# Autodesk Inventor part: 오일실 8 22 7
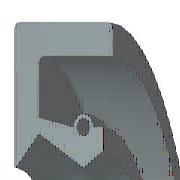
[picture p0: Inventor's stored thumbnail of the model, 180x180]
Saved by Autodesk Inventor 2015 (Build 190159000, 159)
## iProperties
IsCustomPart: 1
Created: 2012-02
Part Number: 오일실 8 22 7
Material: 고무
Description: 오일-실
Document SubType Name: Modeling
Standard: KS B 2804
Designer: mduedu
Standards Organization: KS
Language: ko-KR
Size Designation: D - 8 22 7
Categories: <MemberInstance><Categories><Category DisplayName="샤프트 부품" InternalName="7f7aeb1f-a693-4053-b835-cee3144e0d98" Mnemonic="SHFT"><Category DisplayName="실링" Intern
Density: 0.93 g/cm^3
Appearance: 고무 - 검은색 - 버전 1.1
Mass: 1.28441 g
Surface Area: 18.2787 cm^2
Volume: 1.38108 cm^3
Author: mduedu
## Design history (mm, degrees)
revolve "본체" stored, may be unused: angle "d17" = 90 deg
revolve "스프링1" stored, may be unused: angle "d18" = 90 deg
body "Solid1"
sketch "스케치1"
  geometry: L1 (0, 11)-(7, 11); L2 (7, 9.25)-(1.75, 9.25); L3 (1.75, 5.75)-(4.9, 4); L4 (4.9, 4)-(0, 4); L5 (0, 0)-(9.586, 0) reference; L6 (4.9, 4)-(6.3, 4.875); L7 (0, 18)-(0, -3) reference; L8 (-1.941, 0)-(11.507, 0) reference; L9 (4.2, 6.1)-(1.75, 6.59); L10 (1.75, 6.59)-(1.75, 9.25); L11 (0, 11)-(0, 4.088); L12 (4.9, 4)-(0, 4); L13 (1.75, 5.75)-(0.152, 4.028); L14 (7, 11)-(7, 9.25); L15 (5.6, 6.1)-(6.3, 6.1); L16 (6.3, 6.1)-(6.3, 4.875); C1 r 0.455 at (4.9, 6.1); A1 r 0.7 centre (4.9, 6.1) between (5.6, 6.1) and (4.2, 6.1); A2 r 0.088 centre (0.088, 4.088) between (0, 4.088) and (0.152, 4.028); 1 further point
  constraints: 28 end point, 5 horizontal alignment, 5 point on line, 4 point on circle, 4 vertical alignment, 3 centre point, 3 tangent, 2 collinear, 2 horizontal, 2 perpendicular, 1 coincident, 1 parallel
  dimensions: "d0" = 22 diameter of L1 L5 (= SD2); "d1" = 1.75 distance of L1.end L2.start (= SD); "d2" = 0.91 diameter of C1 (= SPDI); "d3" = 1.4 diameter of A1 (= SPDA); "d4" = 8 diameter of L3.end L5 (= NND); "d5" = 11.5 diameter of L3.start L5 (= TKDM); "d7" = 13.18 diameter of L9.end L5 (= TKDM + 0.24 x SWDT); "d8" = 1.75 distance between parallel lines of L11 L10 (= SD); "d9" = 4.9 distance from line of L11 C1.centre (= SPDST); "d10" = 12.2 diameter of C1.centre L5 (= HLDM); "d11" = 0.0875 radius of A2 (= 0.25 x LAB); "d12" = 6.3 distance between parallel lines of L11 L16 (= SDI); "d13" = 9.75 diameter of L6.end L5 (= ABDM); "d14" = 7 distance from line of L11 L1.end (= SWDT)
fillet "모깎기1" dims "d6" = 0.3 (= RR)
other parameters: "SD2" = 22 [user parameter; used in 1 equation term], "SWDT" = 7 [user parameter; used in 2 equation terms], "RR" = 0.3 [user parameter; used in 1 equation term], "SD" = 1.75 [user parameter; used in 2 equation terms], "NND" = 8 [user parameter; used in 1 equation term], "SPDA" = 1.4 [user parameter; used in 1 equation term], "SPDI" = 0.91 [user parameter; used in 1 equation term], "TKDM" = 11.5 [user parameter; used in 2 equation terms], "HLDM" = 12.2 [user parameter; used in 1 equation term], "ABDM" = 9.75 [user parameter; used in 1 equation term], "SDI" = 6.3 [user parameter; used in 1 equation term], "SPDST" = 4.9 [user parameter; used in 1 equation term], "LAB" = 0.35 [user parameter; used in 1 equation term], "d15" = 0, "d16" = 0, "d19" = 0
